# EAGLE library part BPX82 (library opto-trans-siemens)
Triple PHOTO TRANSISTOR
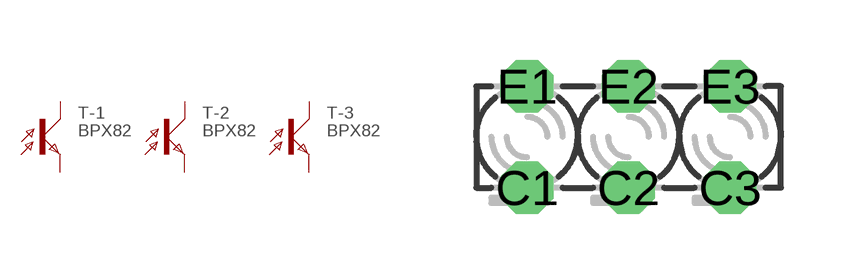
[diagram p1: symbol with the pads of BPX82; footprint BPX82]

Designator prefix T; gates -1=OT-NO -2=OT-NO -3=OT-NO

## BPX82 (OC_FARNELL: unknown; OC_NEWARK: unknown)  [BPX82]
C1  -1:C  pas
C2  -2:C  pas
C3  -3:C  pas
E1  -1:E  pas
E2  -2:E  pas
E3  -3:E  pas

## Footprint BPX82 (pad centres in mm)
Triple PHOTO TRANSISTOR
drill 0.813 octagon: C1 0,-1.27; C2 2.54,-1.27; C3 5.08,-1.27; E1 0,1.27; E2 2.54,1.27; E3 5.08,1.27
